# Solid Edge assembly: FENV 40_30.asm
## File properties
Title: Zylinder
Author: bmolnar
Template: iso assembly.asm
Last saved by: bmolnar
Revision: 14
Application: Solid Edge
Username: bmolnar
Dokumentum tartalom típus: 1
Document Number: FENV 40/30
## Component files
Kit_1.par
Profilrohr.par
Kit_2.par
Kolbenstange.par
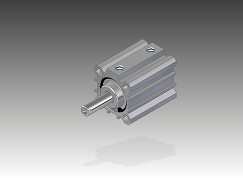
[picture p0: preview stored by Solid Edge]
